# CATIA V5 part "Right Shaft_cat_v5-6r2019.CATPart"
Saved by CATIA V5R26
Part number: Right hand shaft
Bounding box of the stored display mesh (mm): x 0 to 100, y -35 to 35, z -35 to 35
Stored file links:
  D:\_Deepak\CATIA\CATIA V5 2015 Parts Files\Tutorial Files\Tutorials\c16_catia_v5_6r2016_tut\CV joint\Right Shaft_cat_v5-6r2012.CATPart
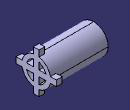
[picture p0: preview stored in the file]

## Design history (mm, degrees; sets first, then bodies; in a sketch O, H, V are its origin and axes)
Body1 (main body)
  Sketch1 on yz-plane, origin (0, 0, 0), H (0, 1, 0), V (0, 0, 1)
    circle A1 centre (0, 0) radius 25
    circle A2 centre (0, 0) radius 17.5
    radius A1 = 25
    radius A2 = 17.5
  Pad1: profile Sketch1, direction (1, 0, 0), length 100
  Sketch2 on end face of Pad1, origin (100, 0, 0), H (0, 1, 0), V (0, 0, 1)
    line L1 (5, 35) -> (5, -35)
    line L2 (5, -35) -> (-5, -35)
    line L3 (-5, -35) -> (-5, 35)
    line L4 (-5, 35) -> (5, 35)
    length L1 = 70
    length L4 = 10
    vertical: L1 V, L3 V
    horizontal: L2 H, L4 H
    equidistance: L1 L3 O, L2 L4 O
  Pad2: profile Sketch2, direction (-1, 0, 0), length 10
  CircPattern1: of the body so far, instances 2, angular step 90, axis from face of Pad1 from Sketch1.A1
